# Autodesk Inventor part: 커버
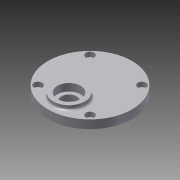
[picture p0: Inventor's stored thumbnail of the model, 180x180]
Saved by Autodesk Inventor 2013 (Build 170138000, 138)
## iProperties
Created: 2015-07
Part Number: 커버
Material: 알루미늄 6061
Document SubType Name: Modeling
Designer: user
Density: 1 g/cm^3
Author: user
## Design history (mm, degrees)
sketch "스케치1"
  geometry: C1 r 40 at (0, 0); 1 further point
  constraints: 1 centre point, 1 coincident
  dimensions: "d1" = 80 diameter of C1
extrude "돌출1" new body sketch "스케치1" distance "d2" = 9; taper "d3" = 0 deg
sketch "스케치2"
  geometry: L1 (0, 0)-(0, -20); C1 r 40 at (0, 0) reference; C2 r 15 at (0, -20)
  constraints: 2 end point, 1 centre point, 1 coincident, 1 vertical
  dimensions: "d5" = 20 distance of L1.start L1.end; "d6" = 30 diameter of C2
extrude "돌출2" join sketch "스케치2" distance "d7" = 4; taper "d8" = 0 deg
sketch "스케치3"
  geometry: C1 r 15 at (0, 0) reference; C2 r 11 at (0, 0); 1 further point
  constraints: 1 centre point, 1 coincident
  dimensions: "d9" = 22 diameter of C2
extrude "돌출3" cut sketch "스케치3" distance "d10" = 7; taper "d11" = 0 deg
sketch "스케치4"
  geometry: L1 (0, 0)-(0, -20); L2 (0, 0)-(0, 11); C1 r 40 at (0, 0) reference; C2 r 14 at (0, 11); C3 r 14 at (0, -20)
  constraints: 4 end point, 2 centre point, 2 coincident, 1 collinear, 1 vertical
  dimensions: "d12" = 20 distance of L1.start L1.end; "d13" = 11 distance of L1.start L2.end; "d14" = 28 diameter of C2; "d15" = 28 diameter of C3
extrude "돌출4" join sketch "스케치4" distance "d16" = 3; taper "d17" = 0 deg
sketch "스케치5"
  geometry: C1 r 14 at (0, 0) reference; C2 r 14 at (0, -31) reference; C3 r 11 at (0, 0); C4 r 11 at (0, -31); 1 further point
  constraints: 2 centre point, 2 coincident
  dimensions: "d18" = 22 diameter of C3; "d19" = 22 diameter of C4
extrude "돌출5" cut sketch "스케치5" distance "d20" = 7; taper "d21" = 0 deg
sketch "스케치6"
  geometry: C1 r 9 at (0, 0); 2 further points
  constraints: 1 centre point, 1 coincident, 1 vertical alignment
  dimensions: "d22" = 18 diameter of C1
extrude "돌출6" cut sketch "스케치6" distance "d23" = 1; taper "d24" = 0 deg
sketch "스케치7"
  geometry: C1 r 11 at (0, 0) reference; C2 r 7.5 at (0, 0); 1 further point
  constraints: 1 centre point, 1 coincident
  dimensions: "d25" = 15 diameter of C2
extrude "돌출7" cut sketch "스케치7" distance "d26" = 2; taper "d27" = 0 deg
fillet "모깎기1" dims "d28" = 2
chamfer "모따기1" distance "d29" = 1; stored, may be unused: second distance "d30" = 2, angle "d31" = 45 deg
fillet "모깎기2" dims "d32" = 2
sketch "스케치8"
  geometry: L1 (0, 0)-(-24.749, 24.749); C1 r 40 at (0, 0) reference
  constraints: 2 end point
  dimensions: "d33" = 35 distance of L1.start L1.end
hole "구멍1" sketch "스케치8" at (-24.749, 24.749) diameter "d35" = 4.5; stored, may be unused: countersink angle "d39" = 90 deg, drill point angle "d41" = 118 deg; dims "d36" = 6, "d37" = 8, "d38" = 4.4, "d40" = 15
node "솔리드1"
pattern_circular "원형 패턴1" dims angle "d43" = 360 deg
node "절단 모서리 투영1"
